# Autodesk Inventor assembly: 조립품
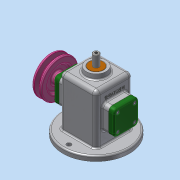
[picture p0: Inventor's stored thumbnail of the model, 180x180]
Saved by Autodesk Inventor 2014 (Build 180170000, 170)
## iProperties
Created: 2021-08
Part Number: 조립품
Document SubType Name: Assembly
Designer: dg
Author: dg
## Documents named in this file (16)
- C:\Users\dg\Desktop\710806V1030\조립품.iam
- C:\Users\dg\Desktop\710806V1030\본체.ipt
- C:\Users\dg\Desktop\710806V1030\V벨트풀리.ipt
- C:\Users\dg\Desktop\710806V1030\고정핀 1.2x8.ipt
- C:\Users\dg\Desktop\710806V1030\뒤커버.ipt
- C:\Users\dg\Desktop\710806V1030\링크.ipt
- C:\Users\dg\Desktop\710806V1030\멈춤나사 M3x8.ipt
- C:\Users\dg\Desktop\710806V1030\베어링 12x32x10.ipt
- C:\Users\dg\Desktop\710806V1030\볼트 M4.ipt
- C:\Users\dg\Desktop\710806V1030\부시.ipt
- C:\Users\dg\Desktop\710806V1030\슬라이드.ipt
- C:\Users\dg\Desktop\710806V1030\앞커버.ipt
- C:\Users\dg\Desktop\710806V1030\오일 실 12 25 7.ipt
- C:\Users\dg\Desktop\710806V1030\키 4x4x10.ipt
- C:\Users\dg\Desktop\710806V1030\편심축.ipt
- C:\Users\dg\Desktop\710806V1030\핀 5x18.ipt
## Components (3 placed, 3 different names)
1. V벨트풀리:1 — 플러쉬:1
2. 고정핀 1.2x8:1
3. 핀 5x18:1
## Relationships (1: Flush 1)
- 플러쉬:1 [Flush]: V벨트풀리:1
